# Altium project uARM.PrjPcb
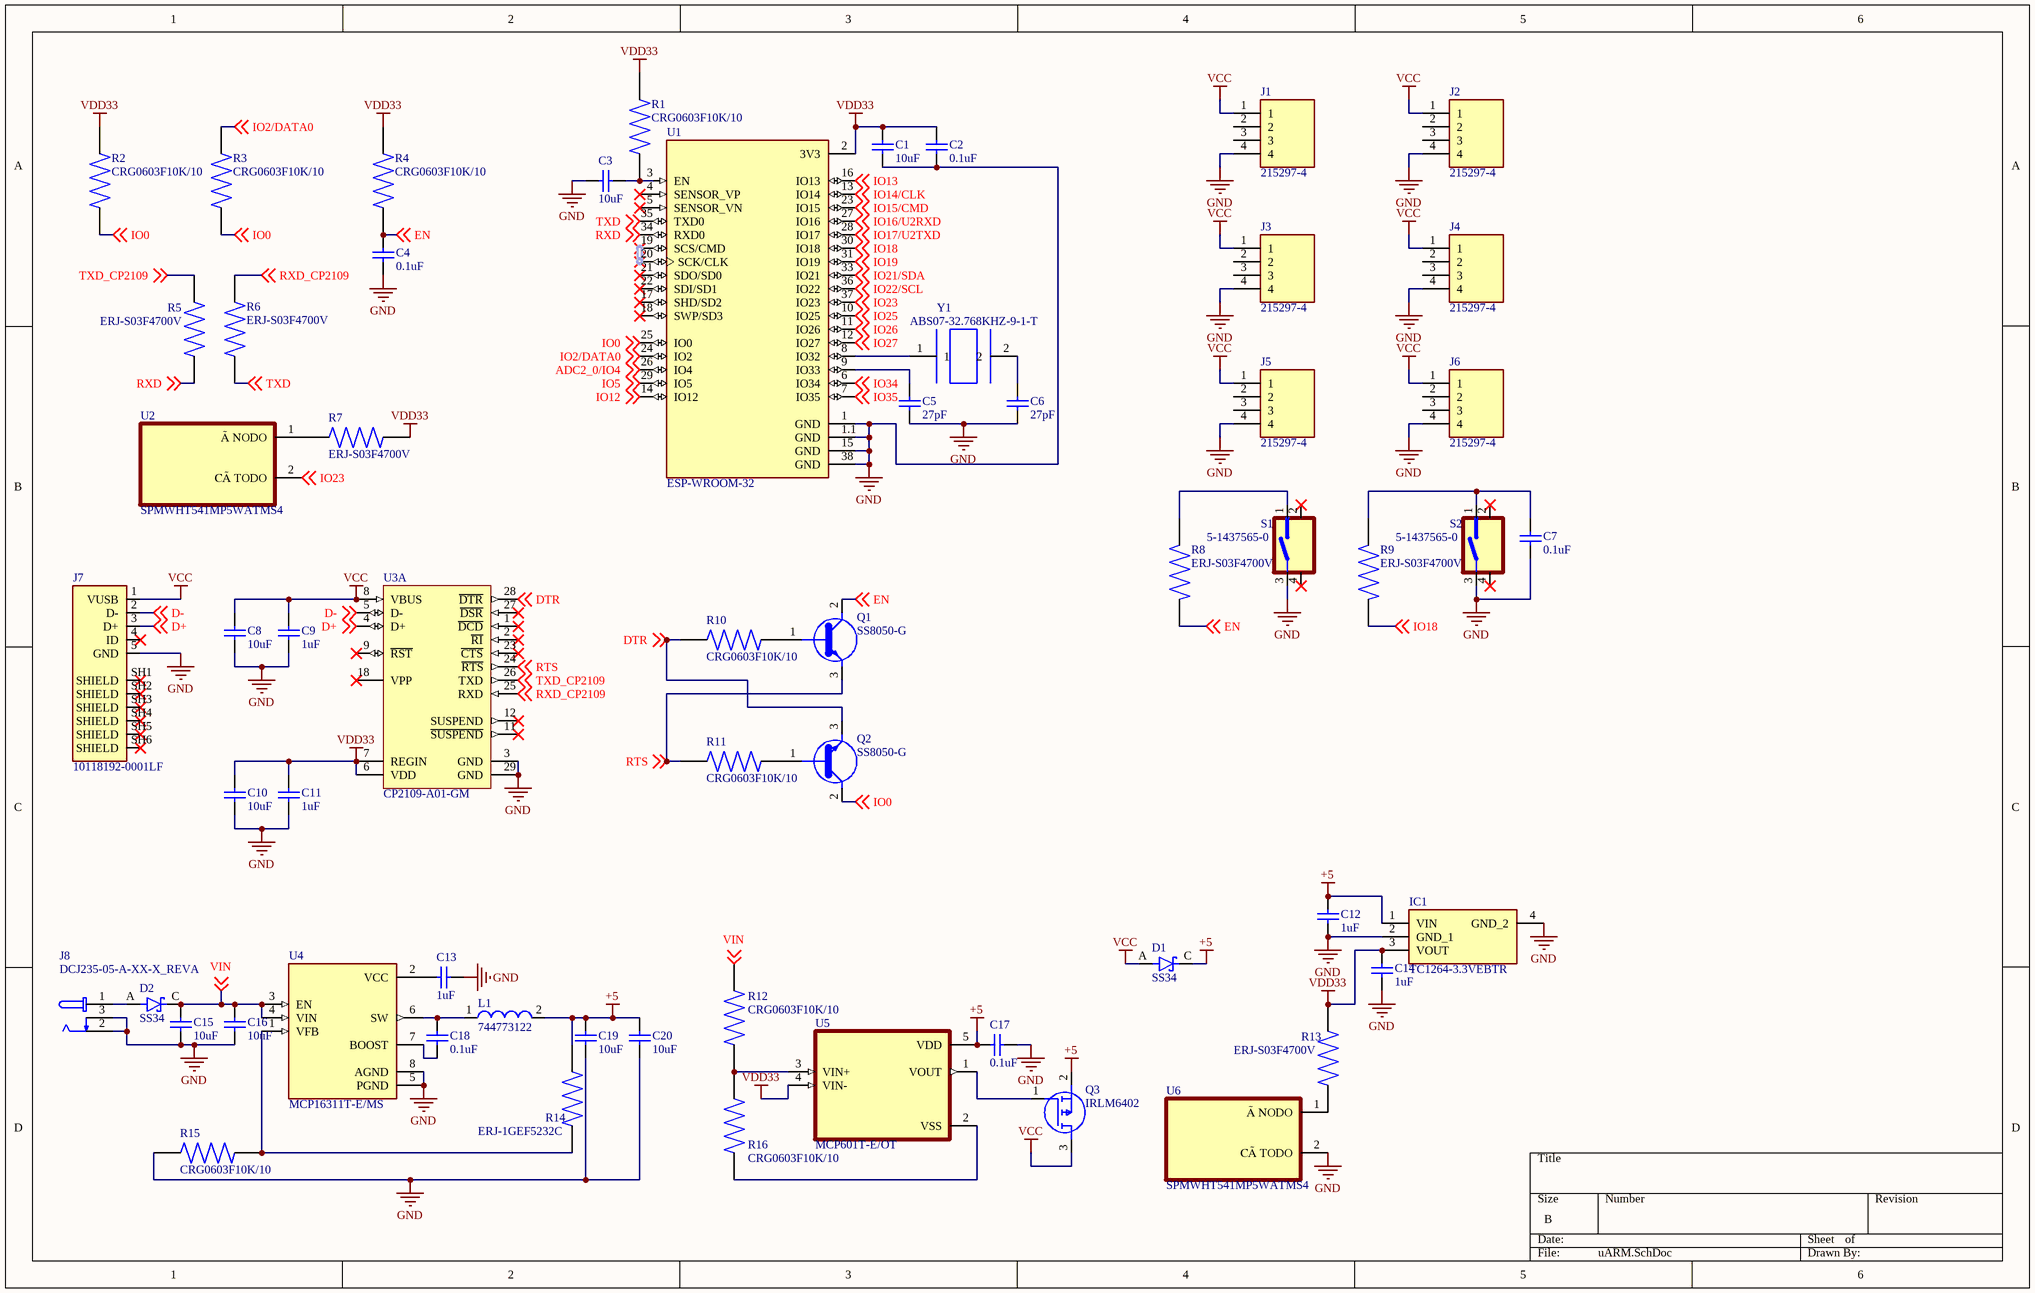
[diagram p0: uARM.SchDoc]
1 sheet, 60 parts. Net scope: global (net labels, ports and power ports of the same name join across sheets).
Board file: PCB1.PcbDoc

## Sheet uARM.SchDoc
size B

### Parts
C1  value 10uF  [C_3216[1206]_N]  (hidden comment: C1206C106K3RACTU)
C2  value 0.1uF  [C_3216[1206]_N]  (hidden comment: C1206C106K3RACTU)
C3  value 10uF  [C_3216[1206]_N]  (hidden comment: C1206C106K3RACTU)
C4  value 0.1uF  [C_3216[1206]_N]  (hidden comment: C1206C106K3RACTU)
C5  value 27pF  [C_3216[1206]_N]  (hidden comment: C1206C106K3RACTU)
C6  value 27pF  [C_3216[1206]_N]  (hidden comment: C1206C106K3RACTU)
C7  value 0.1uF  [C_3216[1206]_N]  (hidden comment: C1206C106K3RACTU)
C8  value 10uF  [C_3216[1206]_N]  (hidden comment: C1206C106K3RACTU)
C9  value 1uF  [C_3216[1206]_N]  (hidden comment: C1206C106K3RACTU)
C10  value 10uF  [C_3216[1206]_N]  (hidden comment: C1206C106K3RACTU)
C11  value 1uF  [C_3216[1206]_N]  (hidden comment: C1206C106K3RACTU)
C12  value 1uF  [C_3216[1206]_N]  (hidden comment: C1206C106K3RACTU)
C13  value 1uF  [C_3216[1206]_N]  (hidden comment: C1206C106K3RACTU)
C14  value 1uF  [C_3216[1206]_N]  (hidden comment: C1206C106K3RACTU)
C15  value 10uF  [C_3216[1206]_N]  (hidden comment: C1206C106K3RACTU)
C16  value 10uF  [C_3216[1206]_N]  (hidden comment: C1206C106K3RACTU)
C17  value 0.1uF  [C_3216[1206]_N]  (hidden comment: C1206C106K3RACTU)
C18  value 0.1uF  [C_3216[1206]_N]  (hidden comment: C1206C106K3RACTU)
C19  value 10uF  [C_3216[1206]_N]  (hidden comment: C1206C106K3RACTU)
C20  value 10uF  [C_3216[1206]_N]  (hidden comment: C1206C106K3RACTU)
D1  SS34  [DIOM7959X265N]
D2  SS34  [DIOM7959X265N]
IC1  TC1264-3.3VEBTR  [TC126433VEBTR]
J1  215297-4  [TE_215297-4]
J2  215297-4  [TE_215297-4]
J3  215297-4  [TE_215297-4]
J4  215297-4  [TE_215297-4]
J5  215297-4  [TE_215297-4]
J6  215297-4  [TE_215297-4]
J7  10118192-0001LF  [AMPHENOL_10118192-0001LF]
J8  DCJ235-05-A-XX-X_REVA  [GCT_DCJ235-05-A-XX-X_REVA]
L1  744773122  [WE-PD2-S]
Q1  SS8050-G  [MBTB-T-SOT23]
Q2  SS8050-G  [MBTB-T-SOT23]
Q3  IRLM6402  [SOT95P237X112-3N]
R1  CRG0603F10K/10  [RESC1608X55N]
R2  CRG0603F10K/10  [RESC1608X55N]
R3  CRG0603F10K/10  [RESC1608X55N]
R4  CRG0603F10K/10  [RESC1608X55N]
R5  ERJ-S03F4700V  [RESC1608X55N]
R6  ERJ-S03F4700V  [RESC1608X55N]
R7  ERJ-S03F4700V  [RESC1608X55N]
R8  ERJ-S03F4700V  [RESC1608X55N]
R9  ERJ-S03F4700V  [RESC1608X55N]
R10  CRG0603F10K/10  [RESC1608X55N]
R11  CRG0603F10K/10  [RESC1608X55N]
R12  CRG0603F10K/10  [RESC1608X55N]
R13  ERJ-S03F4700V  [RESC1608X55N]
R14  ERJ-1GEF5232C  [RESC0603X26N]
R15  CRG0603F10K/10  [RESC1608X55N]
R16  CRG0603F10K/10  [RESC1608X55N]
S1  5-1437565-0  [SW_5-1437565-0]
S2  5-1437565-0  [SW_5-1437565-0]
U1  ESP-WROOM-32  [MODULE_ESP-WROOM-32]
U2  SPMWHT541MP5WATMS4  [LED_SPMWHT541MP5WAPKS4]
U3  CP2109-A01-GM  [SLAB-QFN-28-3125x3125TP_L]  (part A of 2)
U4  MCP16311T-E/MS  [SOP65P490X110-8N]
U5  MCP601T-E/OT  [SOT95P270X145-5N]
U6  SPMWHT541MP5WATMS4  [LED_SPMWHT541MP5WAPKS4]
Y1  ABS07-32.768KHZ-9-1-T  [XTAL320X150X90]

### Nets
+5: C12.1 C17.2 C19.2 C20.2 D1.C(K) IC1.1(VIN) L1.2 Q3.2(S) R14.2 U5.5(VDD)
GND: C1.1 C2.1 C3.2 C4.1 C5.1 C6.1 C7.1 C8.1 C9.1 C10.1 C11.1 C12.2 C13.1 C14.2 C15.1 C16.1 C17.1 C19.1 C20.1 IC1.2(GND_1) IC1.4(GND_2) J1.4 J2.4 J3.4 J4.4 J5.4 J6.4 J7.5(GND) J8.2 J8.3 R15.1 S1.3 S2.3 U1.1(GND) U1.1.1(GND) U1.15(GND) U1.38(GND) U3.3(GND) U3.29(GND) U4.5(PGND) U4.8(AGND) U6.2(CÃTODO)
VCC: C8.2 C9.2 D1.A J1.1 J2.1 J3.1 J4.1 J5.1 J6.1 J7.1(VUSB) Q3.3(D) U3.8(VBUS)
VDD33: C1.2 C2.2 C10.2 C11.2 C14.1 IC1.3(VOUT) R1.2 R2.1 R4.1 R7.1 R13.2 U1.2(3V3) U3.6(VDD) U3.7(REGIN) U5.4(VIN-)
ADC2_0/IO4: U1.26(IO4) ; off-sheet ADC2_0/IO4
D+: J7.3(D+) U3.4(D+) ; off-sheet D+
D-: J7.2(D-) U3.5(D-) ; off-sheet D-
DTR: Q2.3(C) R10.2 U3.28(~{DTR}) ; off-sheet DTR
EN: C4.2 Q1.2(E) R4.2 R8.2 ; off-sheet EN
IO0: Q2.2(E) R2.2 R3.2 U1.25(IO0) ; off-sheet IO0
IO2/DATA0: R3.1 U1.24(IO2) ; off-sheet IO2/DATA0
IO5: U1.29(IO5) ; off-sheet IO5
IO12: U1.14(IO12) ; off-sheet IO12
IO13: U1.16(IO13) ; off-sheet IO13
IO14/CLK: U1.13(IO14) ; off-sheet IO14/CLK
IO15/CMD: U1.23(IO15) ; off-sheet IO15/CMD
IO16/U2RXD: U1.27(IO16) ; off-sheet IO16/U2RXD
IO17/U2TXD: U1.28(IO17) ; off-sheet IO17/U2TXD
IO18: R9.2 U1.30(IO18) ; off-sheet IO18
IO19: U1.31(IO19) ; off-sheet IO19
IO21/SDA: U1.33(IO21) ; off-sheet IO21/SDA
IO22/SCL: U1.36(IO22) ; off-sheet IO22/SCL
IO23: U1.37(IO23) U2.2(CÃTODO) ; off-sheet IO23
IO25: U1.10(IO25) ; off-sheet IO25
IO26: U1.11(IO26) ; off-sheet IO26
IO27: U1.12(IO27) ; off-sheet IO27
IO34: U1.6(IO34) ; off-sheet IO34
IO35: U1.7(IO35) ; off-sheet IO35
RTS: Q1.3(C) R11.2 U3.24(~{RTS}) ; off-sheet RTS
RXD: R5.1 U1.34(RXD0) ; off-sheet RXD
RXD_CP2109: R6.2 U3.25(RXD) ; off-sheet RXD_CP2109
TXD: R6.1 U1.35(TXD0) ; off-sheet TXD
TXD_CP2109: R5.2 U3.26(TXD) ; off-sheet TXD_CP2109
VIN: C15.2 C16.2 D2.C(K) R12.1 U4.3(EN) U4.4(VIN) ; off-sheet VIN
NetC3_1: C3.1 R1.1 U1.3(EN)
NetC5_2: C5.2 U1.9(IO33)
NetC6_2: C6.2 Y1.2
NetC7_2: C7.2 R9.1 S2.1
NetC13_2: C13.2 U4.2(VCC)
NetC18_1: C18.1 U4.7(BOOST)
NetC18_2: C18.2 L1.1 U4.6(SW)
NetD2_A: D2.A J8.1
NetQ1_1: Q1.1(B) R10.1
NetQ2_1: Q2.1(B) R11.1
NetQ3_1: Q3.1(G) U5.1(VOUT)
NetR7_2: R7.2 U2.1(ÃNODO)
NetR8_1: R8.1 S1.1
NetR12_2: R12.2 R16.1 U5.3(VIN+)
NetR13_1: R13.1 U6.1(ÃNODO)
NetR14_1: R14.1 R15.2 U4.1(VFB)
NetR16_2: R16.2 U5.2(VSS)
NetU1_8: U1.8(IO32) Y1.1

Not connected (* = marked no-connect by the designer): J1 2 3; J2 2 3; J3 2 3; J4 2 3; J5 2 3; J6 2 3; J7 4(ID)* SH1(SHIELD)* SH2(SHIELD)* SH3(SHIELD)* SH4(SHIELD)* SH5(SHIELD)* SH6(SHIELD)*; S1 2* 4(1)*; S2 2* 4(1)*; U1 4(SENSOR_VP)* 5(SENSOR_VN)* 17(SHD/SD2)* 18(SWP/SD3)* 19(SCS/CMD)* 20(SCK/CLK)* 21(SDO/SD0)* 22(SDI/SD1)*; U3 1(~{DCD})* 2(~{RI})* 9(~{RST})* 11(~{SUSPEND})* 12(SUSPEND)* 18(VPP)* 23(~{CTS})* 27(~{DSR})*

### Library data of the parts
C1-C20 = C_10uf_3216[1206]: Capacitor Céramique 10uf XR7 25V 10%; Manufacturer: KEMET
D1 D2 = SS34: Diode Schottky 40V 3A 2-Pin SMC T/R; MF: {'manufacturer': u'ON Semiconductor'}
IC1 = TC1264-3.3VEBTR: Integrated Circuit; Manufacturer_Name: Microchip
J1-J6 = 215297-4: MF: {'manufacturer': u'TE Connectivity'}
J7 = 10118192-0001LF: Single Port 5 Contact Horizontal Right Angle Shielded Micro B USB 2.0 Connector; MF: {'manufacturer': u'FCI'}
J8 = DCJ235-05-A-XX-X_REVA: DC Power Jack, Thru-Hole, Horizontal, with Locating Pegs, D2.35mm; MF: {'manufacturer': u'Global Connector Technology'}
L1 = 744773122: SMD Power Inductor WE-PD2, L = 22.0 µH; Inductance: 22.0 ÂµH
Q1 Q2 = SS8050-G: <b>Bipolar Transistors - BJT NPN TRANSISTOR 1.5A 40V</b><p> Source: <a href="https://componentsearchengine.com/Datasheets/1/SS8050-G.pdf"> Datasheet </a>; MF: {'manufacturer': u'Comchip Technology'}
Q3 = IRLM6402: MOSFET (P-Channel); Manufacturer_Name: Infineon
R1-R4 R10-R12 R15 R16 = CRG0603F10K/10: Thick Film Resistors - SMD CRG0603 1% 10K 10K RL; MF: {'manufacturer': u'TE Connectivity'}
R5-R9 R13 = ERJ-S03F4700V: MF: {'manufacturer': u'Panasonic'}
R14 = ERJ-1GEF5232C: Res Thick Film 0201 52.3K Ohm 1% 0.05W(1/20W) Â±200ppm/C SMD T/R; MF: {'manufacturer': u'Panasonic'}
S1 S2 = 5-1437565-0: Switch Tactile OFF (ON) Round Button Gull Wing 0.05A 12VDC 1.57N SMD T/R; MF: {'manufacturer': u'TE Connectivity'}
U1 = ESP-WROOM-32: Module: combo; GPIO, I2C x2, I2S x2, SDIO, SPI x3, UART x3; 19.5dBm; MF: {'manufacturer': u'Espressif Systems'}
U2 U6 = SPMWHT541MP5WATMS4: MF: {'manufacturer': u'Samsung Semiconductor,'}
U3 = CP2109-A01-GM: Single-Chip USB to UART Bridge, 1024 Bytes EEPROM, -40 to 85 degC, 28-pin QFN, Tube; Manufacturer: Silicon Labs; Sub-Family: USB Bridges; Internal Oscillator: TRUE
U4 = MCP16311T-E/MS: The MCP16311/2 is a compact, high-efficiency, fixed frequency, synchronous step-down DC-DC converter in an 8-pin MSOP, or 2 x 3 TDFN package that operates from input voltage sources up to 30V. Integrated features include a high-side and a low-side switch, fixed frequency peak current mode control, internal compensation, peak current limit and overtemperature protection. The MCP16311/2 provides all the active functions for local DC-DC conversion, with fast transient response and accurate regulation.; MF: {'manufacturer': u'Microchip Technology'}
U5 = MCP601T-E/OT: MF: {'manufacturer': u'Microchip'}
Y1 = ABS07-32.768KHZ-9-1-T: ABS07 Series 32.768 kHz Â±20 ppm 12.5 pF -40 to +85 C SMT Low Profile Crystal; MF: {'manufacturer': u'Abracon'}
